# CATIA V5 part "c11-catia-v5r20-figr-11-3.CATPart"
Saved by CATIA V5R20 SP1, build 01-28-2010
Part number: Part1
Bounding box of the stored display mesh (mm): x -50 to 50, y -98.731 to 72.975, z 0 to 120
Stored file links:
  D:\v5_r20\psrt_files_downloaded\c11\c11-catia-v5r20-figr-11-3.CATPart
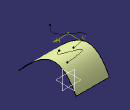
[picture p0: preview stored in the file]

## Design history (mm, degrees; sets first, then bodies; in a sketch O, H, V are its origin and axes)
Set1
  Sketch1 on yz-plane, origin (0, 0, 0), H (0, 1, 0), V (0, 0, 1)
    spline S1 through (-98.7309, 0) (-73.2816, 27.1192) (0, 74.8227) (72.975, 18.624)
    point P1 (-98.7309, 0)
    point P2 (0, 74.8227)
    coincidence: P1 H, P2 V
  Extrude1: Element1 Sketch1, Lim1 50, Lim2 50, Direction yz-plane
  Plane1: type Offset, RefPlane xy-plane, Offset 120
  Sketch2 on Plane1, origin (0, 0, 120), H (1, 0, 0), V (0, 1, 0)
    spline S1 through (28.7787, 44.6229) (-22.3035, 19.7059) (20.5049, -22.8447) (5.396, -48.9118)
  Project1: ToProject Sketch2, Support Extrude1
Body1 (main body)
